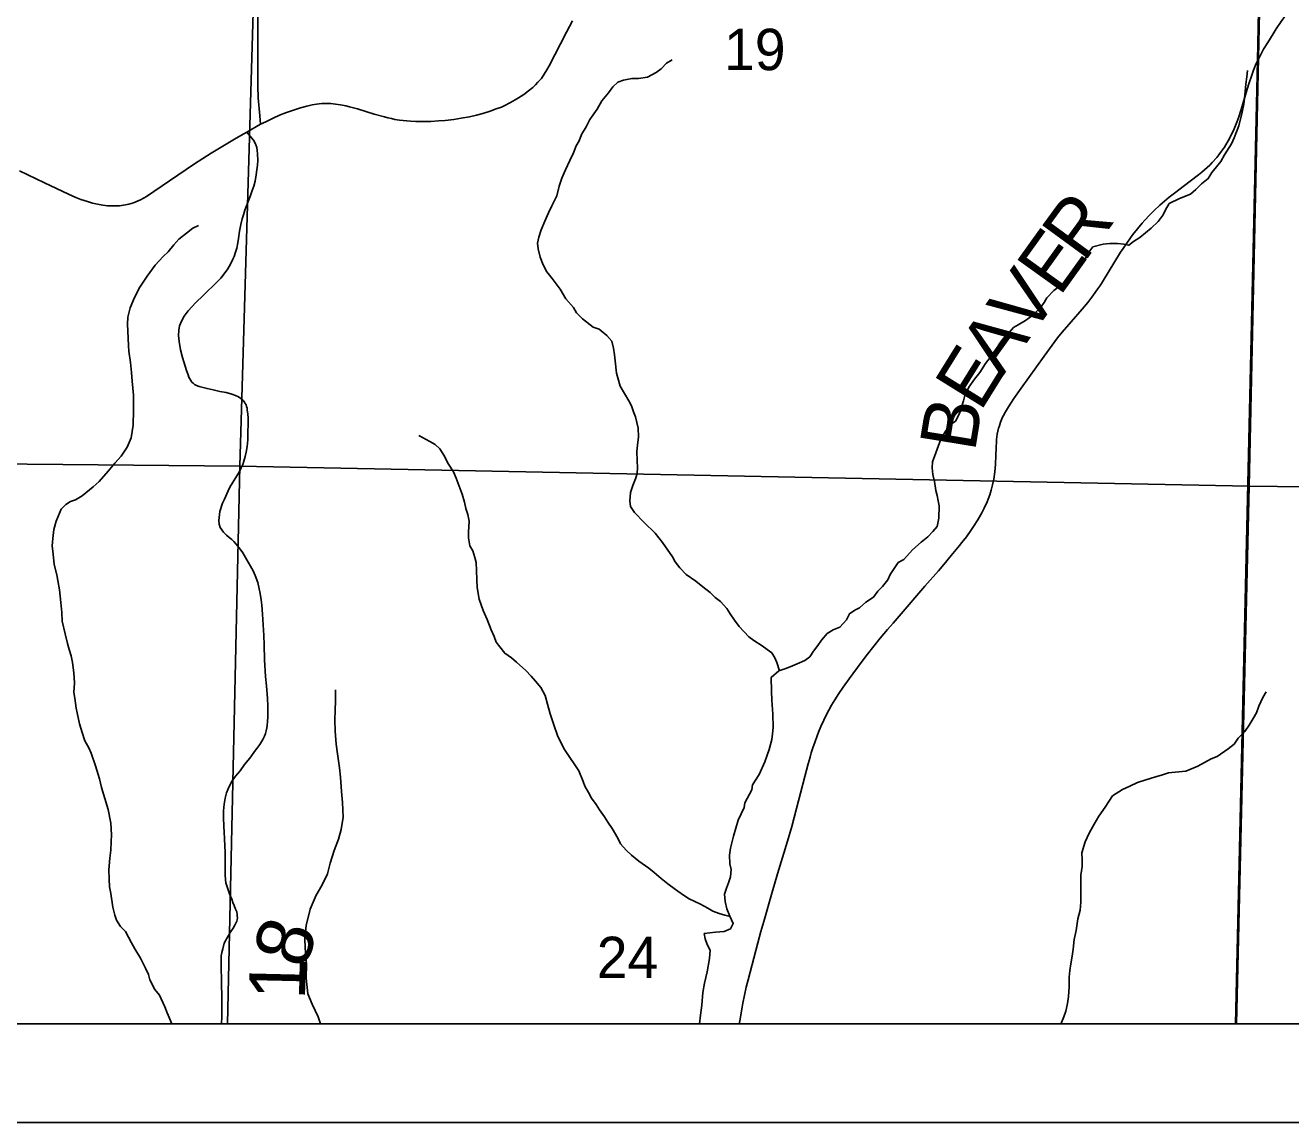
# Model space of a CAD drawing. Extents: x -1.2 to 34, y -8.5 to 22.
# Drawn here: x 7.031 to 8.311, y 14 to 15.11 of the extents above; entities that cross this region are included whole.
import ezdxf

# ---------------------------------------------------------------- set-up
doc = ezdxf.new("R2010")
doc.units = 0
for name, color, linetype in [('GM_X_County_Road', 7, 'Continuous'), ('GM_X_County_Road_Text', 7, 'Continuous'), ('GM_X_Minor_River', 7, 'Continuous'), ('GM_X_Section', 7, 'Continuous'), ('GM_X_Section_Text', 7, 'Continuous'), ('GM_X_Township_Road', 7, 'Continuous'), ('GM_X_Township_Road_Text', 7, 'Continuous'), ('GM_X_Unincorporated_Text', 7, 'Continuous'), ('SH_Cut_Line', 7, 'Continuous'), ('SH_Data', 7, 'Continuous')]:
    doc.layers.add(name, color=color, linetype=linetype)

msp = doc.modelspace()

# ---------------------------------------------------------------- linework, layer by layer
at = {"layer": 'GM_X_County_Road'}
msp.add_line((7.255, 15.0017), (7.269, 15.0099), dxfattribs=at)
for points in [[(8.2835, 15.0857), (8.2877, 15.0927), (8.2931, 15.1013), (8.2961, 15.1063), (8.3013, 15.1137), (8.3057, 15.1197), (8.3118, 15.1279), (8.3164, 15.1339), (8.3213, 15.1405), (8.3247, 15.1451), (8.3287, 15.1506), (8.3323, 15.1554), (8.3356, 15.16), (8.339, 15.1649), (8.3432, 15.1706), (8.3459, 15.1743)], [(7.269, 15.0099), (7.2741, 15.0124), (7.2816, 15.0161), (7.2882, 15.019), (7.2953, 15.0218), (7.3033, 15.0245), (7.3092, 15.0264), (7.3157, 15.0282), (7.3211, 15.0294), (7.3255, 15.0301), (7.3309, 15.0307), (7.3347, 15.0309), (7.3399, 15.0307), (7.3448, 15.0302), (7.3498, 15.0295), (7.355, 15.0285), (7.3589, 15.0275), (7.3671, 15.0253), (7.3838, 15.0202), (7.3943, 15.0172), (7.3975, 15.0164), (7.4012, 15.0156), (7.4048, 15.0147), (7.4093, 15.0141), (7.4131, 15.0136), (7.4205, 15.0129), (7.4259, 15.0128), (7.4346, 15.0127), (7.441, 15.0128), (7.4488, 15.0132), (7.4555, 15.0137), (7.4644, 15.0148), (7.4717, 15.0159), (7.4803, 15.0175), (7.4872, 15.0191), (7.4938, 15.0209), (7.5013, 15.0232), (7.5074, 15.0253), (7.5127, 15.0273), (7.5152, 15.0284), (7.5216, 15.0317), (7.5264, 15.0344), (7.5299, 15.0365), (7.5352, 15.0401), (7.5401, 15.0438), (7.5442, 15.047), (7.5469, 15.0496), (7.5495, 15.0524), (7.553, 15.0562), (7.5559, 15.0604), (7.5586, 15.0649), (7.5608, 15.0689), (7.5722, 15.0911), (7.5783, 15.1031), (7.5846, 15.1146)], [(8.1179, 14.8462), (8.1207, 14.8506), (8.1388, 14.8804), (8.1413, 14.8842), (8.1488, 14.8949), (8.1514, 14.8983), (8.1608, 14.9098), (8.1635, 14.9129), (8.1681, 14.9178), (8.1729, 14.9225), (8.1786, 14.928), (8.1855, 14.9341), (8.188, 14.9362), (8.1947, 14.9412), (8.2021, 14.9469), (8.2178, 14.9586), (8.2211, 14.9614), (8.229, 14.9685), (8.2315, 14.9711), (8.2362, 14.9763), (8.2382, 14.9788), (8.2408, 14.9825), (8.2438, 14.9867), (8.2452, 14.989), (8.2476, 14.993), (8.2503, 14.9983), (8.2536, 15.0052), (8.2566, 15.0121), (8.2584, 15.0172), (8.2606, 15.0239), (8.2626, 15.0305), (8.2652, 15.0395), (8.267, 15.0455), (8.269, 15.0519), (8.2712, 15.0586), (8.2733, 15.0646), (8.2746, 15.0681), (8.2761, 15.0713), (8.2786, 15.0765), (8.2814, 15.0816), (8.2835, 15.0857)], [(7.025, 14.9626), (7.0505, 14.9506), (7.0747, 14.939), (7.082, 14.9357), (7.087, 14.9338), (7.0937, 14.9316), (7.0989, 14.9302), (7.104, 14.929), (7.1093, 14.9281), (7.1142, 14.9275), (7.1184, 14.9273), (7.1263, 14.9275), (7.1324, 14.9284), (7.1355, 14.9291), (7.1404, 14.9305), (7.1427, 14.9313), (7.1473, 14.9334), (7.1511, 14.9354), (7.1536, 14.9369), (7.1768, 14.9526), (7.2022, 14.9699), (7.2188, 14.9807), (7.234, 14.9898), (7.2441, 14.9958), (7.2521, 15.0001), (7.255, 15.0017)], [(7.7531, 14.1), (7.7536, 14.103), (7.7559, 14.1167), (7.7567, 14.1209), (7.7602, 14.1369), (7.762, 14.1444), (7.7698, 14.1741), (7.7719, 14.1818), (7.7751, 14.1935), (7.7779, 14.2036), (7.7863, 14.2331), (7.7919, 14.2517), (7.8019, 14.2848), (7.8062, 14.2997), (7.811, 14.3177), (7.815, 14.3332), (7.8195, 14.35), (7.8229, 14.3631), (7.8248, 14.3697), (7.826, 14.3741), (7.8279, 14.3801), (7.8295, 14.3845), (7.8319, 14.3912), (7.8333, 14.3948), (7.8357, 14.4007), (7.8387, 14.4071), (7.8412, 14.4122), (7.8465, 14.4222), (7.8498, 14.4278), (7.8538, 14.434), (7.8582, 14.4404), (7.8642, 14.4489), (7.8764, 14.4654), (7.883, 14.474), (7.8891, 14.4818), (7.8958, 14.49), (7.9032, 14.4987), (7.9088, 14.5053), (7.9148, 14.5123), (7.9408, 14.5425), (7.9545, 14.5583), (7.9599, 14.5646), (7.9676, 14.5738), (7.9759, 14.5837), (7.9784, 14.5869), (7.983, 14.5926), (7.9873, 14.599), (7.9901, 14.6031), (7.9944, 14.6098), (7.9985, 14.6169), (8.0009, 14.6215), (8.004, 14.6281), (8.005, 14.6306), (8.0067, 14.6351), (8.0081, 14.6396), (8.0094, 14.645), (8.0105, 14.651), (8.0115, 14.6582), (8.0122, 14.6657), (8.0127, 14.6753), (8.013, 14.6823), (8.0133, 14.6897), (8.0135, 14.6911), (8.0141, 14.6963), (8.0155, 14.7023), (8.0159, 14.7037), (8.0174, 14.7084), (8.0195, 14.7135), (8.0204, 14.7154), (8.0224, 14.7191), (8.0254, 14.724), (8.0309, 14.7323), (8.0383, 14.743), (8.0614, 14.7753), (8.0695, 14.7863), (8.0752, 14.7939), (8.0797, 14.7995), (8.0887, 14.8099), (8.1001, 14.8229), (8.1058, 14.8297), (8.1097, 14.8349), (8.1173, 14.8454), (8.1179, 14.8462)]]:
    msp.add_lwpolyline(points, dxfattribs=at)
at = {"layer": 'GM_X_Minor_River'}
msp.add_line((8.2829, 14.4301), (8.2862, 14.4359), dxfattribs=at)
for points in [[(7.6851, 15.075), (7.6795, 15.0715), (7.6743, 15.066), (7.669, 15.0622), (7.6604, 15.0575), (7.6513, 15.0562), (7.6445, 15.0561), (7.6362, 15.0544), (7.6302, 15.0524), (7.6253, 15.0478), (7.6208, 15.0416), (7.6142, 15.0335), (7.6094, 15.0251), (7.6019, 15.0147), (7.5983, 15.0074), (7.5934, 14.9994), (7.5913, 14.9932), (7.5883, 14.9879), (7.5854, 14.981), (7.5817, 14.9733), (7.5773, 14.9637), (7.5736, 14.9553), (7.5711, 14.9473), (7.5686, 14.9373), (7.5635, 14.9273), (7.5601, 14.9204), (7.5565, 14.912), (7.5528, 14.9032), (7.5503, 14.8956), (7.5492, 14.8895), (7.5497, 14.8838), (7.5517, 14.8754), (7.5549, 14.8675), (7.5584, 14.8607), (7.5638, 14.8539), (7.568, 14.8486), (7.5719, 14.843), (7.5777, 14.8332), (7.5854, 14.8245), (7.5885, 14.8192), (7.5946, 14.8132), (7.6054, 14.8047), (7.6115, 14.8025), (7.6191, 14.7961), (7.6241, 14.7905), (7.6258, 14.7833), (7.627, 14.7768), (7.6275, 14.7704), (7.6291, 14.7582), (7.6304, 14.7533), (7.6327, 14.7449), (7.637, 14.7374), (7.6413, 14.7302), (7.644, 14.7249), (7.646, 14.7189), (7.6483, 14.714), (7.6508, 14.7026), (7.6513, 14.6938), (7.6503, 14.6854), (7.6496, 14.679), (7.6498, 14.6694), (7.6502, 14.6626), (7.6499, 14.6565), (7.6481, 14.6511), (7.6456, 14.6446), (7.643, 14.6374), (7.6424, 14.629), (7.6432, 14.6233), (7.6471, 14.6173), (7.6571, 14.6071), (7.6682, 14.5963), (7.6756, 14.5869), (7.6856, 14.5722), (7.6883, 14.5673), (7.693, 14.5612), (7.6995, 14.5545), (7.7091, 14.5478), (7.7164, 14.5418), (7.7236, 14.5362), (7.7286, 14.5313), (7.734, 14.5272), (7.7405, 14.5201), (7.744, 14.5148), (7.7483, 14.5084), (7.7529, 14.502), (7.7629, 14.4915), (7.7679, 14.4878), (7.7763, 14.4822), (7.7813, 14.4785), (7.7862, 14.4751), (7.789, 14.4702), (7.7913, 14.4653), (7.7939, 14.4571)], [(7.9518, 14.6774), (7.9569, 14.6912), (7.9613, 14.6989), (7.9661, 14.7054), (7.9717, 14.7097), (7.9758, 14.7174), (7.9798, 14.73), (7.9812, 14.7354), (7.9853, 14.7438), (7.9912, 14.7519), (7.9964, 14.7588), (8.0023, 14.7677), (8.0083, 14.7757), (8.0131, 14.7823), (8.0168, 14.7884), (8.0209, 14.7938), (8.0261, 14.7992), (8.0306, 14.8042), (8.0354, 14.807), (8.0426, 14.8113), (8.0501, 14.8167), (8.0579, 14.8245), (8.0616, 14.8295), (8.0642, 14.8344), (8.0713, 14.8418), (8.0769, 14.8461), (8.0818, 14.8499), (8.0881, 14.8546), (8.0941, 14.8619), (8.1, 14.8681), (8.103, 14.8739), (8.1067, 14.8804), (8.1108, 14.8858), (8.1213, 14.8886), (8.1281, 14.8891), (8.1357, 14.8892), (8.1422, 14.8885), (8.1471, 14.8875), (8.152, 14.8914), (8.1583, 14.8953), (8.1699, 14.9046), (8.177, 14.9115), (8.1819, 14.9184), (8.1844, 14.9234), (8.1881, 14.9296), (8.1983, 14.9347), (8.2096, 14.939), (8.2148, 14.9437), (8.2208, 14.9495), (8.2275, 14.9549), (8.2312, 14.9611), (8.2357, 14.9668), (8.2401, 14.9722), (8.2438, 14.9788), (8.2509, 14.9899), (8.2538, 14.9961), (8.256, 15.0022), (8.2585, 15.0083), (8.2617, 15.0221), (8.2635, 15.0301), (8.2642, 15.0362), (8.2648, 15.043), (8.2655, 15.0503), (8.2665, 15.0579), (8.2672, 15.0644)], [(7.1403, 14.7357), (7.139, 14.7501), (7.1385, 14.7589), (7.1372, 14.7688), (7.1355, 14.7805), (7.1354, 14.7859), (7.1349, 14.7935), (7.1345, 14.8007), (7.1344, 14.8075), (7.1346, 14.8148), (7.1371, 14.8243), (7.1415, 14.8347), (7.1467, 14.845), (7.1541, 14.8562), (7.1623, 14.8673), (7.1705, 14.8762), (7.1753, 14.8808), (7.1813, 14.8878), (7.1861, 14.8936), (7.194, 14.8998), (7.2003, 14.9048), (7.206, 14.9076)], [(7.1792, 14.1), (7.1744, 14.1112), (7.1721, 14.1173), (7.1666, 14.129), (7.162, 14.1346), (7.1569, 14.1444), (7.1557, 14.1498), (7.1526, 14.1562), (7.1475, 14.1664), (7.1417, 14.1758), (7.1382, 14.1819), (7.1323, 14.1932), (7.1273, 14.1984), (7.1231, 14.2048), (7.1215, 14.2098), (7.1195, 14.2181), (7.1174, 14.2318), (7.1162, 14.2386), (7.1157, 14.2462), (7.1155, 14.2557), (7.1165, 14.2676), (7.1175, 14.2756), (7.1178, 14.2843), (7.118, 14.2912), (7.1175, 14.303), (7.1146, 14.3166), (7.1114, 14.328), (7.1079, 14.339), (7.1059, 14.3477), (7.1019, 14.361), (7.0975, 14.3738), (7.0952, 14.3791), (7.0913, 14.3863), (7.0885, 14.3946), (7.0857, 14.4034), (7.0833, 14.4144), (7.0825, 14.4193), (7.0812, 14.4292), (7.08, 14.4352), (7.0806, 14.4448), (7.0801, 14.455), (7.0788, 14.4653), (7.0775, 14.4721), (7.0752, 14.4786), (7.0736, 14.4846), (7.0712, 14.4945), (7.0683, 14.5074), (7.0678, 14.5161), (7.0669, 14.526), (7.0656, 14.5389), (7.0639, 14.5484), (7.0627, 14.5541), (7.0603, 14.5647), (7.059, 14.575), (7.0581, 14.5834), (7.0588, 14.591), (7.0598, 14.6001), (7.0623, 14.6085), (7.0671, 14.6204), (7.0719, 14.6251), (7.0768, 14.6282), (7.0817, 14.6301), (7.0884, 14.6341), (7.0997, 14.643), (7.1056, 14.6484), (7.1146, 14.6588), (7.1216, 14.6669), (7.128, 14.6742), (7.1339, 14.6834), (7.1379, 14.6926), (7.14, 14.7056), (7.1405, 14.7208), (7.1403, 14.7357)], [(7.429, 14.6951), (7.4401, 14.6891), (7.4454, 14.6858), (7.4504, 14.6817), (7.4543, 14.6753), (7.459, 14.6662), (7.464, 14.6583), (7.4668, 14.6518), (7.4699, 14.6439), (7.4727, 14.6356), (7.4751, 14.6276), (7.4767, 14.6212), (7.4787, 14.6151), (7.4799, 14.6083), (7.4796, 14.6026), (7.4793, 14.5976), (7.4794, 14.5915), (7.4806, 14.5835), (7.4837, 14.5783), (7.4857, 14.5718), (7.4869, 14.5665), (7.4874, 14.5585), (7.4876, 14.549), (7.4881, 14.5414), (7.4901, 14.5296), (7.4941, 14.5179), (7.498, 14.5088), (7.5023, 14.4986), (7.5051, 14.4918), (7.5074, 14.4861), (7.5109, 14.4812), (7.5159, 14.4748), (7.5228, 14.47), (7.5278, 14.4659), (7.5374, 14.4573), (7.5428, 14.4516), (7.547, 14.4464), (7.5524, 14.44), (7.5567, 14.4321), (7.5591, 14.4233), (7.5619, 14.4135), (7.5654, 14.4025), (7.5694, 14.3915), (7.5729, 14.384), (7.5764, 14.3775), (7.5818, 14.3693), (7.5861, 14.3628), (7.5907, 14.3557), (7.5954, 14.3451), (7.597, 14.3402), (7.6005, 14.3338), (7.6036, 14.3281), (7.6083, 14.3217), (7.6117, 14.3164), (7.6168, 14.3093), (7.6203, 14.304), (7.6245, 14.2976), (7.6303, 14.2878), (7.6331, 14.2821), (7.6388, 14.2757), (7.6442, 14.2705), (7.6515, 14.2645), (7.6618, 14.2574), (7.6672, 14.2529), (7.6741, 14.2469), (7.681, 14.2417), (7.6886, 14.2357), (7.6967, 14.2302), (7.7024, 14.2264), (7.7138, 14.2209), (7.7215, 14.2168), (7.7264, 14.2139), (7.7329, 14.2117), (7.7386, 14.2099), (7.7438, 14.2084)], [(7.713, 14.1), (7.714, 14.1086), (7.7153, 14.1189), (7.7163, 14.1315), (7.718, 14.141), (7.7205, 14.1525), (7.723, 14.1662), (7.7236, 14.1746), (7.7205, 14.1803), (7.7185, 14.186), (7.7177, 14.1913), (7.729, 14.1926), (7.7377, 14.1935), (7.7441, 14.1959), (7.7471, 14.2016), (7.7436, 14.2088), (7.7404, 14.2164), (7.7388, 14.2236), (7.7383, 14.2312), (7.7401, 14.2373), (7.7423, 14.2426), (7.7441, 14.2488), (7.7448, 14.256), (7.7435, 14.2617), (7.7434, 14.2704), (7.7441, 14.2777), (7.7473, 14.2899), (7.752, 14.306), (7.7582, 14.3186), (7.7589, 14.3236), (7.7659, 14.3366), (7.7666, 14.3416), (7.7733, 14.352), (7.7791, 14.365), (7.7835, 14.3776), (7.786, 14.3876), (7.7867, 14.3933), (7.7873, 14.3998), (7.7871, 14.4131), (7.7862, 14.4275), (7.7857, 14.4363), (7.7855, 14.4504), (7.7933, 14.4569), (7.7993, 14.4589), (7.8046, 14.4609), (7.8118, 14.4641), (7.8193, 14.4676), (7.8245, 14.4711), (7.8282, 14.4769), (7.8327, 14.4827), (7.8364, 14.488), (7.842, 14.4946), (7.848, 14.4985), (7.8548, 14.5013), (7.8615, 14.5086), (7.8648, 14.5147), (7.87, 14.5182), (7.8749, 14.5206), (7.8813, 14.5264), (7.8888, 14.5315), (7.8932, 14.5376), (7.8981, 14.5423), (7.9033, 14.5492), (7.9059, 14.5546), (7.914, 14.5665), (7.9196, 14.5696), (7.9282, 14.5793), (7.9372, 14.587), (7.9439, 14.5924), (7.9488, 14.5978), (7.9532, 14.6029), (7.955, 14.6113), (7.9552, 14.6238), (7.9544, 14.6288), (7.9532, 14.6345), (7.9519, 14.6394), (7.9507, 14.6485), (7.9491, 14.6557), (7.9482, 14.6622), (7.9485, 14.6683), (7.9518, 14.6774)], [(7.7894, 14.4677), (7.7894, 14.4679)], [(7.3297, 14.1), (7.3271, 14.107), (7.321, 14.1199), (7.3168, 14.1302), (7.3149, 14.1462), (7.3153, 14.1602), (7.3141, 14.1765), (7.3137, 14.1864), (7.3152, 14.1993), (7.319, 14.216), (7.3251, 14.2301), (7.3308, 14.24), (7.3365, 14.2517), (7.3392, 14.2624), (7.3433, 14.2753), (7.3479, 14.2867), (7.3506, 14.2965), (7.3525, 14.3091), (7.3517, 14.3239), (7.3509, 14.3349), (7.3497, 14.3493), (7.3486, 14.3588), (7.3467, 14.3729), (7.3455, 14.3827), (7.3444, 14.396), (7.344, 14.4074), (7.3443, 14.4169), (7.3447, 14.4268), (7.3447, 14.4378)], [(8.0785, 14.1), (8.0791, 14.1012), (8.0816, 14.107), (8.0834, 14.1127), (8.0852, 14.1204), (8.0862, 14.1276), (8.0869, 14.1375), (8.0867, 14.147), (8.0874, 14.1539), (8.0884, 14.1608), (8.0898, 14.1684), (8.0908, 14.1756), (8.0918, 14.1852), (8.094, 14.1943), (8.0957, 14.2062), (8.0978, 14.2149), (8.0985, 14.2229), (8.0988, 14.2287), (8.0987, 14.2363), (8.0988, 14.2504), (8.0999, 14.2591), (8.1001, 14.266), (8.0997, 14.2728), (8.1029, 14.2839), (8.1069, 14.2927), (8.1121, 14.3019), (8.1169, 14.31), (8.1232, 14.3192), (8.1306, 14.3304), (8.1407, 14.337), (8.1483, 14.3402), (8.1558, 14.3441), (8.1697, 14.3485), (8.1814, 14.3517), (8.1874, 14.3537), (8.1942, 14.3546), (8.2048, 14.3555), (8.2169, 14.3606), (8.2304, 14.3681), (8.2364, 14.3704), (8.2477, 14.3782), (8.2537, 14.3829), (8.2577, 14.389), (8.2645, 14.3956), (8.2689, 14.4021), (8.273, 14.4087), (8.2763, 14.4144), (8.2788, 14.4213), (8.2829, 14.4301)]]:
    msp.add_lwpolyline(points, dxfattribs=at)
at = {"layer": 'GM_X_Section'}
for points in [[(7.2776, 15.674), (7.2479, 14.6639), (6.2441, 14.6736), (6.2657, 15.6908)], [(8.2912, 15.6653), (8.2689, 14.6439), (7.2479, 14.6639), (7.2776, 15.674)], [(8.9, 14.6363), (8.9, 15.6494), (8.2912, 15.6653), (8.2689, 14.6439)], [(6.2289, 14.1), (7.2356, 14.1), (7.2479, 14.6639), (6.2441, 14.6736)], [(7.2356, 14.1), (8.2562, 14.1), (8.2689, 14.6439), (7.2479, 14.6639)], [(8.2562, 14.1), (8.9, 14.1), (8.9, 14.6363), (8.2689, 14.6439)]]:
    msp.add_lwpolyline(points, close=True, dxfattribs=at)
at = {"layer": 'GM_X_Township_Road'}
msp.add_line((7.255, 15.0017), (7.269, 15.0099), dxfattribs=at)
for points in [[(7.269, 15.0099), (7.2682, 15.0183), (7.2666, 15.0365), (7.2664, 15.04), (7.2663, 15.0449), (7.2661, 15.1342)], [(7.2295, 14.1), (7.2296, 14.1075), (7.2298, 14.1253), (7.2294, 14.1424), (7.229, 14.1586), (7.2291, 14.1644), (7.2292, 14.1688), (7.2298, 14.1721), (7.2306, 14.1757), (7.2322, 14.1815), (7.2351, 14.1871), (7.2383, 14.1925), (7.2413, 14.1967), (7.2433, 14.2005), (7.2449, 14.2038), (7.2452, 14.2052), (7.2455, 14.2071), (7.2454, 14.209), (7.2452, 14.2107), (7.2448, 14.2132), (7.2436, 14.2161), (7.2422, 14.2197), (7.241, 14.2226), (7.2398, 14.2259), (7.2375, 14.2313), (7.2357, 14.2364), (7.2338, 14.2426), (7.2335, 14.2456), (7.2332, 14.2506), (7.2332, 14.2553), (7.2331, 14.2733), (7.2326, 14.2871), (7.2321, 14.2937), (7.2317, 14.2994), (7.2314, 14.3085), (7.2315, 14.3155), (7.2321, 14.3222), (7.2332, 14.3282), (7.2346, 14.3337), (7.236, 14.3378), (7.2379, 14.3414), (7.2401, 14.3456), (7.2437, 14.3505), (7.2482, 14.356), (7.2526, 14.3622), (7.258, 14.3687), (7.2639, 14.3766), (7.2652, 14.3783), (7.2681, 14.3825), (7.2711, 14.3875), (7.2728, 14.3908), (7.2738, 14.3936), (7.2745, 14.3964), (7.2751, 14.3992), (7.2755, 14.4016), (7.2759, 14.4056), (7.2763, 14.4101), (7.2764, 14.4156), (7.2763, 14.4217), (7.2759, 14.429), (7.2748, 14.4418), (7.274, 14.4513), (7.273, 14.4681), (7.2725, 14.4832), (7.2721, 14.4929), (7.2717, 14.5036), (7.2709, 14.5143), (7.2703, 14.5234), (7.2695, 14.5289), (7.2684, 14.5353), (7.2675, 14.5398), (7.266, 14.5463), (7.2636, 14.5535), (7.2614, 14.5583), (7.2589, 14.5629), (7.2565, 14.5669), (7.2509, 14.5762), (7.2482, 14.5802), (7.2441, 14.5852), (7.2418, 14.5877), (7.2397, 14.5898), (7.2372, 14.5918), (7.2346, 14.5942), (7.2314, 14.5974), (7.2282, 14.6019), (7.2269, 14.6054), (7.2267, 14.609), (7.2276, 14.6181), (7.2305, 14.6265), (7.2323, 14.6307), (7.236, 14.6392), (7.2378, 14.6427), (7.2404, 14.6471), (7.244, 14.6524), (7.2475, 14.6586), (7.2494, 14.6623), (7.251, 14.6658), (7.2521, 14.669), (7.2534, 14.6738), (7.2542, 14.6782), (7.2552, 14.6839), (7.2559, 14.6905), (7.2562, 14.6969), (7.2564, 14.7079), (7.2563, 14.7127), (7.256, 14.7169), (7.2555, 14.7207), (7.2552, 14.7227), (7.2548, 14.7243), (7.2542, 14.7259), (7.2534, 14.7273), (7.2525, 14.7289), (7.2514, 14.7303), (7.2491, 14.7323), (7.2466, 14.734), (7.2437, 14.7354), (7.2399, 14.7367), (7.2341, 14.7384), (7.2278, 14.7397), (7.2211, 14.7412), (7.2149, 14.7425), (7.2095, 14.7439), (7.2068, 14.7446), (7.2042, 14.7456), (7.2022, 14.7467), (7.2008, 14.748), (7.1995, 14.7491), (7.1983, 14.7508), (7.1974, 14.7522), (7.1965, 14.7541), (7.1956, 14.7565), (7.194, 14.7608), (7.1927, 14.7651), (7.19, 14.774), (7.188, 14.7816), (7.1865, 14.79), (7.1858, 14.7962), (7.1861, 14.8016), (7.1869, 14.8059), (7.1888, 14.8106), (7.1917, 14.8156), (7.1958, 14.8213), (7.2035, 14.8297), (7.211, 14.8367), (7.2255, 14.8508), (7.2288, 14.8543), (7.2332, 14.8598), (7.2357, 14.8637), (7.2384, 14.8684), (7.241, 14.8734), (7.2422, 14.8762), (7.2437, 14.8804), (7.245, 14.8845), (7.2459, 14.8898), (7.2465, 14.8944), (7.2476, 14.9017), (7.2489, 14.9083), (7.2503, 14.9142), (7.2515, 14.9184), (7.253, 14.9228), (7.2548, 14.9274), (7.2588, 14.9378), (7.2605, 14.9428), (7.262, 14.9474), (7.2633, 14.9523), (7.2645, 14.9586), (7.2653, 14.9639), (7.2657, 14.9686), (7.266, 14.9731), (7.2659, 14.98), (7.2655, 14.9834), (7.265, 14.9864), (7.2641, 14.989), (7.2631, 14.9914), (7.2616, 14.9937), (7.2581, 14.9981), (7.2563, 15.0003), (7.255, 15.0017)]]:
    msp.add_lwpolyline(points, dxfattribs=at)
at = {"layer": 'GM_X_Unincorporated_Text'}
for p, q in [((8.2772, 15.0742), (8.2794, 15.1757)), ((8.2551, 14.1), (8.2772, 15.0742)), ((2.3586, 14.1), (8.2551, 14.1))]:
    msp.add_line(p, q, dxfattribs=at)
msp.add_lwpolyline([(8.2551, 14.1), (8.9, 14.1), (8.9, 17.6758), (8.3326, 17.6871), (8.3265, 17.2224), (8.3029, 16.2873), (8.2955, 15.9378), (8.2794, 15.1757), (8.2772, 15.0742)], close=True, dxfattribs=at)
at = {"layer": 'SH_Cut_Line'}
msp.add_lwpolyline([(2.3586, 14.1), (8.9, 14.1), (8.9, 17.6758), (8.3326, 17.6871), (7.9782, 17.6941), (7.8111, 17.6977), (7.3722, 17.707), (7.1254, 17.7122), (6.7322, 17.7204), (6.6751, 17.7216), (6.665, 17.7216)], dxfattribs=at)
at = {"layer": 'SH_Data'}
for p, q in [((2.1, 14.1), (8.9, 14.1)), ((2.1, 14.1), (8.9, 14.1)), ((2, 14), (9, 14)), ((2, 14), (9, 14))]:
    msp.add_line(p, q, dxfattribs=at)

# ---------------------------------------------------------------- texts
at = {"layer": 'GM_X_County_Road_Text'}
for s, rotation, p in [('R', 53.8108, (8.1018, 14.8691)), ('E', 54.3353, (8.0771, 14.8346)), ('V', 54.3374, (8.0479, 14.794)), ('A', 54.395, (8.0188, 14.7534)), ('E', 58.1182, (7.9969, 14.7181)), ('B', 80.6814, (7.9914, 14.6775))]:
    msp.add_text(s, height=0.0568, rotation=rotation, dxfattribs=at).set_placement(p)
at = {"layer": 'GM_X_Section_Text'}
for s, p in [('19', (7.7377, 15.0646)), ('24', (7.609, 14.1462))]:
    msp.add_text(s, height=0.04186, rotation=0, dxfattribs=at).set_placement(p)
at = {"layer": 'GM_X_Township_Road_Text'}
for s, rotation, p in [('8', 71.9225, (7.3139, 14.1542)), ('1', 88.678, (7.3138, 14.1238))]:
    msp.add_text(s, height=0.0568, rotation=rotation, dxfattribs=at).set_placement(p)

doc.saveas('drawing.dxf')
